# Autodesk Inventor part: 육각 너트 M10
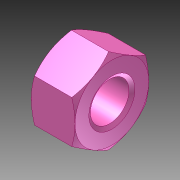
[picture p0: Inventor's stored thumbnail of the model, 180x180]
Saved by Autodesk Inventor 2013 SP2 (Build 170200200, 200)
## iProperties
Created: 2025-04
Part Number: 육각 너트 M10
Material: Generic
Document SubType Name: Modeling
Designer: 601
Density: 1 g/cm^3
Author: 601
변환 표준: STEP AP214IS
전처리기: Build: 200, Release: 2013 SP2 Update 6 - Date: Thu 07/17/2014
전송 단위: 밀리미터
불확실성: 0.01
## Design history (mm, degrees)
node "육각 너트 M101"
body "Solid1"
node "기준1"
